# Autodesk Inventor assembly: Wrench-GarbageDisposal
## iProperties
Created: 2005-01
Part Number: Wrench-GarbageDisposal
Document SubType Name: Assembly
Designer: Dale Schneider
Manufacturer: Standard
Standards Organization: Custom
Author: Dale Schneider
